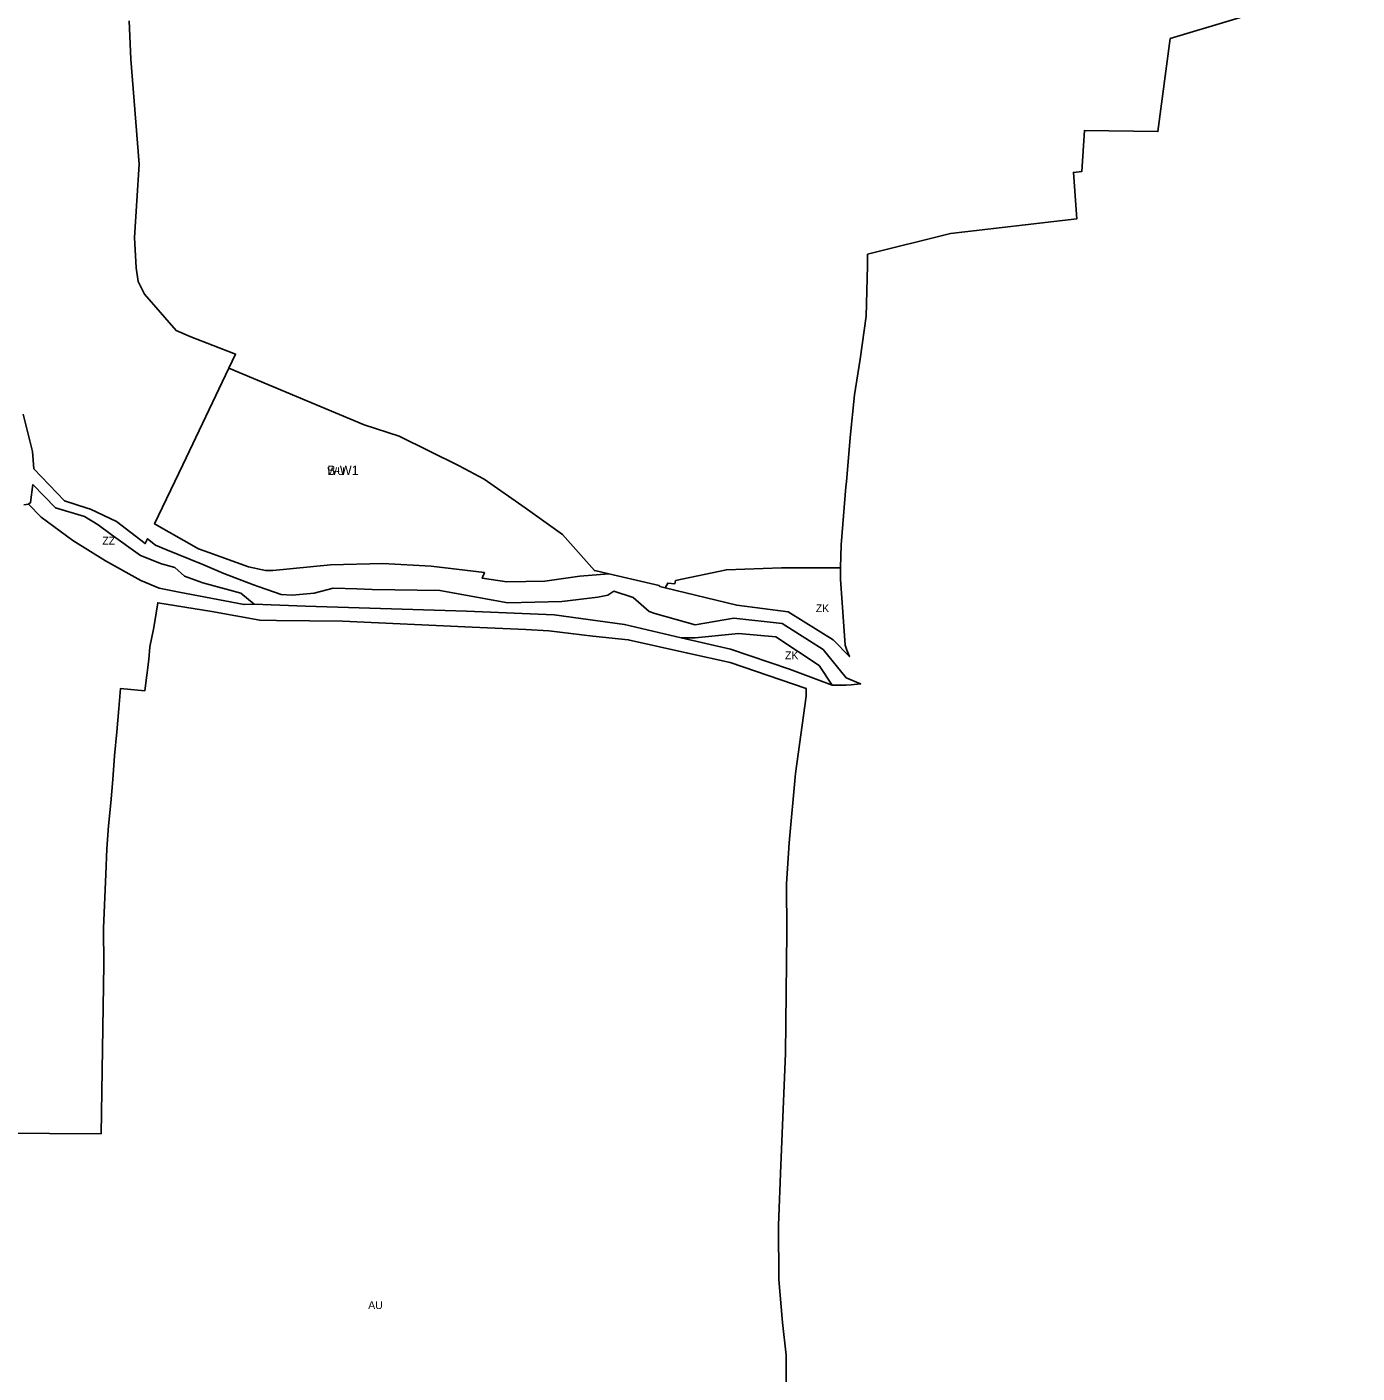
# Model space of a CAD drawing. Extents: x -532067 to -529270, y -1180561 to -1176456.
# Drawn here: x -530284 to -529433, y -1178979 to -1178117 of the extents above; entities that cross this region are included whole.
import ezdxf

# ---------------------------------------------------------------- set-up
doc = ezdxf.new("R2010")
doc.units = 0
for name, color, linetype in [('90630013', 7, 'Continuous'), ('90630023', 7, 'Continuous'), ('90670013', 7, 'Continuous'), ('90710013', 7, 'Continuous'), ('90750013', 7, 'Continuous'), ('ID_navrh', 7, 'Continuous')]:
    doc.layers.add(name, color=color, linetype=linetype)

msp = doc.modelspace()

# ---------------------------------------------------------------- linework, layer by layer
at = {"layer": '90630013'}
msp.add_lwpolyline([(-530285.9453, -1178365.16245), (-530280.1173, -1178388.96345), (-530279.0763, -1178400.02945), (-530259.5113, -1178420.49045), (-530244.9823, -1178425.22645), (-530242.8593, -1178425.91845), (-530226.2083, -1178433.85245), (-530207.9263, -1178447.96045), (-530206.4423, -1178444.85245), (-530201.3833, -1178448.91245), (-530194.6383, -1178451.61845), (-530171.0303, -1178461.25945), (-530157.5403, -1178467.01045), (-530138.6543, -1178474.28345), (-530135.0563, -1178475.62045), (-530121.0273, -1178480.58645), (-530113.8753, -1178480.86245), (-530099.8463, -1178479.75845), (-530087.7433, -1178476.44745), (-530072.5663, -1178476.94945), (-530062.7113, -1178477.27545), (-530019.3613, -1178477.92145), (-529975.8773, -1178485.75045), (-529941.3123, -1178484.91145), (-529918.4553, -1178482.11545), (-529912.0443, -1178480.99745), (-529908.1413, -1178478.48045), (-529895.8773, -1178482.39545), (-529885.5633, -1178491.34245), (-529881.9753, -1178492.59745), (-529856.1913, -1178499.98645), (-529831.3293, -1178495.59945), (-529800.4813, -1178499.06345), (-529774.2373, -1178515.68945), (-529759.5033, -1178533.93145), (-529750.3513, -1178537.74545), (-529756.2703, -1178538.40545), (-529759.5573, -1178538.51545), (-529768.4353, -1178538.51545), (-529776.8663, -1178525.95145), (-529804.6123, -1178507.64845), (-529828.3583, -1178505.39145), (-529856.1043, -1178508.14945), (-529865.1033, -1178508.14945), (-529901.3483, -1178499.62445), (-529946.3413, -1178493.60745), (-530002.4003, -1178491.12945), (-530105.4673, -1178487.98345), (-530138.2703, -1178486.68845), (-530146.8303, -1178479.56945), (-530171.0283, -1178472.94945), (-530182.7613, -1178468.78145), (-530188.8713, -1178463.14245), (-530197.4263, -1178460.93645), (-530210.8703, -1178455.54245), (-530229.6903, -1178442.05745), (-530238.0013, -1178435.92845), (-530246.8003, -1178430.53445), (-530265.3763, -1178425.14045), (-530279.7973, -1178410.18445), (-530281.2643, -1178421.70745), (-530282.4863, -1178422.68845), (-530285.6743, -1178423.23545)], dxfattribs=at)
at = {"layer": '90630023'}
msp.add_lwpolyline([(-529911.2873, -1178467.35745), (-529929.8503, -1178468.87045), (-529952.3703, -1178472.07045), (-529976.6803, -1178472.34045), (-529992.4003, -1178470.04045), (-529990.9103, -1178466.48045), (-530025.0403, -1178462.39045), (-530055.8203, -1178460.71045), (-530089.4603, -1178461.49045), (-530126.2103, -1178465.25045), (-530130.9903, -1178465.08045), (-530141.9503, -1178462.75045), (-530167.2603, -1178453.72045), (-530173.9303, -1178451.34045), (-530201.9133, -1178435.37145), (-530183.8213, -1178397.49245), (-530154.4243, -1178335.78745), (-530067.9153, -1178372.01045), (-530045.4653, -1178379.25845), (-530007.0153, -1178398.15445), (-529991.0163, -1178406.69645), (-529964.9523, -1178425.07445), (-529940.9533, -1178442.15845), (-529920.5673, -1178465.19545), (-529920.2753, -1178465.26345)], close=True, dxfattribs=at)
at = {"layer": '90670013'}
msp.add_lwpolyline([(-530138.2703, -1178486.68845), (-530144.6313, -1178486.92445), (-530186.1833, -1178479.07945), (-530198.8933, -1178476.38245), (-530210.6253, -1178471.47845), (-530233.3573, -1178458.97445), (-530254.1333, -1178445.98045), (-530274.4203, -1178431.02445), (-530282.4863, -1178422.68845), (-530281.2643, -1178421.70745), (-530279.7973, -1178410.18445), (-530265.3763, -1178425.14045), (-530246.8003, -1178430.53445), (-530238.0013, -1178435.92845), (-530229.6903, -1178442.05745), (-530210.8703, -1178455.54245), (-530197.4263, -1178460.93645), (-530188.8713, -1178463.14245), (-530182.7613, -1178468.78145), (-530171.0283, -1178472.94945), (-530146.8303, -1178479.56945)], close=True, dxfattribs=at)
at = {"layer": '90710013'}
for points in [[(-529763.1033, -1178470.60645), (-529760.1553, -1178512.82845), (-529759.0093, -1178516.19945), (-529757.3903, -1178520.22845), (-529767.8893, -1178509.56345), (-529796.6193, -1178491.58945), (-529829.5533, -1178487.39045), (-529875.2113, -1178476.19945), (-529873.6873, -1178473.20045), (-529869.0833, -1178473.66245), (-529868.6233, -1178471.58345), (-529836.1633, -1178464.65645), (-529800.9413, -1178463.50145), (-529763.2213, -1178463.39145), (-529763.1033, -1178466.11245)], [(-529776.8663, -1178525.95145), (-529768.4353, -1178538.51545), (-529795.8633, -1178528.20845), (-529833.6073, -1178515.42045), (-529865.1033, -1178508.14945), (-529856.1043, -1178508.14945), (-529828.3583, -1178505.39145), (-529804.6123, -1178507.64845)]]:
    msp.add_lwpolyline(points, close=True, dxfattribs=at)
at = {"layer": '90750013'}
for points in [[(-529432.6943, -1178088.77845), (-529552.1533, -1178124.84145), (-529560.0893, -1178184.37345), (-529607.1593, -1178183.72045), (-529608.6783, -1178209.83045), (-529614.1003, -1178210.48245), (-529611.9313, -1178240.07345), (-529692.7363, -1178249.55845), (-529745.8233, -1178262.77245), (-529745.8233, -1178270.26645), (-529746.6933, -1178302.34745), (-529750.5573, -1178329.90645), (-529754.2063, -1178352.72945), (-529756.9963, -1178380.07345), (-529759.3563, -1178408.33445), (-529759.7813, -1178411.60245), (-529762.7563, -1178448.69245), (-529763.2213, -1178463.39145), (-529800.9413, -1178463.50145), (-529836.1633, -1178464.65645), (-529868.6233, -1178471.58345), (-529869.0833, -1178473.66245), (-529873.6873, -1178473.20045), (-529875.2113, -1178476.19945), (-529878.6403, -1178475.35945), (-529879.1523, -1178474.84645), (-529911.2873, -1178467.35745), (-529920.2753, -1178465.26345), (-529920.5673, -1178465.19545), (-529940.9533, -1178442.15845), (-529964.9523, -1178425.07445), (-529991.0163, -1178406.69645), (-530007.0153, -1178398.15445), (-530045.4653, -1178379.25845), (-530067.9153, -1178372.01045), (-530154.4243, -1178335.78745), (-530150.1113, -1178326.73345), (-530178.8193, -1178315.64945), (-530188.2193, -1178311.53945), (-530208.3353, -1178288.40145), (-530212.4393, -1178280.16945), (-530213.7103, -1178271.52945), (-530214.6993, -1178252.18345), (-530211.8243, -1178205.26545), (-530217.2033, -1178137.99345), (-530218.2293, -1178113.53445)], [(-530302.3453, -1178825.24745), (-530236.1433, -1178825.58045), (-530234.4203, -1178717.34745), (-530234.6123, -1178693.97245), (-530233.1463, -1178659.44945), (-530232.4723, -1178643.34845), (-530231.3243, -1178628.53645), (-530230.0153, -1178613.87745), (-530228.7073, -1178598.78145), (-530227.6163, -1178583.68545), (-530226.0893, -1178568.37045), (-530224.7803, -1178553.49245), (-530223.6903, -1178540.58445), (-530208.2113, -1178542.10845), (-530205.6693, -1178522.00845), (-530205.0713, -1178514.00645), (-530202.6783, -1178502.60345), (-530202.0793, -1178499.00245), (-530199.8863, -1178485.79845), (-530165.3853, -1178491.40045), (-530134.6733, -1178497.00145), (-530123.9043, -1178497.20145), (-530081.6263, -1178497.60145), (-529998.8033, -1178501.45245), (-529964.4903, -1178502.82845), (-529949.6213, -1178503.74645), (-529921.4843, -1178507.18845), (-529898.9593, -1178509.44445), (-529860.8673, -1178518.07345), (-529833.6293, -1178524.03145), (-529785.0073, -1178540.72445), (-529785.0073, -1178545.59145), (-529792.0203, -1178594.94745), (-529795.9993, -1178639.36845), (-529797.7293, -1178665.74345), (-529797.4373, -1178696.58345), (-529798.4343, -1178774.21245), (-529801.2823, -1178845.71245), (-529802.7693, -1178884.07845), (-529802.5573, -1178918.82145), (-529800.2193, -1178946.31745), (-529797.8273, -1178967.16945), (-529798.1793, -1179002.39145)]]:
    msp.add_lwpolyline(points, dxfattribs=at)

# ---------------------------------------------------------------- texts
at = {"layer": '90630023'}
msp.add_text('WU', height=5, rotation=359.99999997, dxfattribs=at).set_placement((-530091.45347, -1178404.06395))
at = {"layer": '90670013'}
msp.add_text('ZZ', height=5, rotation=0.00000002, dxfattribs=at).set_placement((-530235.32034, -1178448.55445))
at = {"layer": '90710013'}
for p in [(-529778.94484, -1178491.80995), (-529798.62601, -1178521.95345)]:
    msp.add_text('ZK', height=5, rotation=359.99999999, dxfattribs=at).set_placement(p)
at = {"layer": '90750013'}
msp.add_text('AU', height=5, rotation=359.99999995, dxfattribs=at).set_placement((-530065.2638, -1178937.69851))
at = {"layer": 'ID_navrh'}
msp.add_text('B-W1', height=6, rotation=359.99999998, dxfattribs=at).set_placement((-530091.45347, -1178404.06395))

doc.saveas('drawing.dxf')
